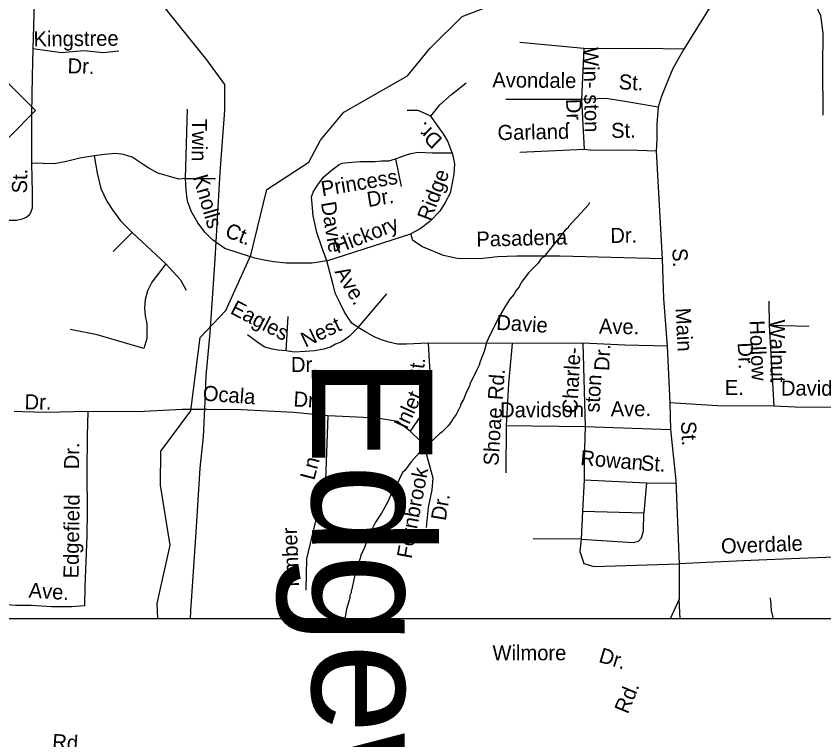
# Model space of a CAD drawing. Extents: x 1553981 to 1780076, y 812965 to 996873.
# Drawn here: x 1632965 to 1633602, y 844957 to 845527 of the extents above; entities that cross this region are included whole.
import ezdxf

# ---------------------------------------------------------------- set-up
doc = ezdxf.new("R2010")
doc.units = 0
for name, color, linetype in [('Default', 7, 'Continuous'), ('Exist Hydrographic Creek Single Shore', 7, 'Continuous'), ('Exist Hydrographic Misc Water Feature', 7, 'Continuous'), ('Exist Road Non-System Type 51 Label', 7, 'Continuous'), ('Exist Utilities Electrical Transmission Line', 7, 'Continuous'), ('Map Preparation Border County Name Lower Right Label', 7, 'Continuous'), ('Map Preparation Border Division and District Label', 7, 'Continuous')]:
    doc.layers.add(name, color=color, linetype=linetype)

msp = doc.modelspace()

# ---------------------------------------------------------------- linework, layer by layer
at = {"layer": 'Default'}
msp.add_lwpolyline([(1632323.05, 848155.4), (1636375.85, 848155.4), (1636375.85, 845052.3), (1632323.05, 845052.3)], close=True, dxfattribs=at)
at = {"layer": 'Exist Hydrographic Creek Single Shore'}
for points in [[(1633273.69, 845479.99), (1633291.58, 845501.65), (1633316.82, 845526.57), (1633348.33, 845538.66), (1633384.82, 845546.53), (1633399.58, 845555.67), (1633434.46, 845603.38), (1633448.33, 845633.05), (1633450.71, 845655.16), (1633439.83, 845696.82), (1633436.7, 845700.17), (1633439.07, 845729.25), (1633449.95, 845766.78)], [(1633077, 845052.3), (1633076.43, 845064.43), (1633086.7, 845110.25), (1633078.95, 845157.59), (1633079.31, 845184.22), (1633103.01, 845216.14), (1633110.34, 845273.94), (1633130.6, 845295.08), (1633150.08, 845338.75), (1633162.66, 845390.39), (1633195.83, 845411.91), (1633205.04, 845429.12), (1633223.46, 845451.25), (1633273.69, 845479.99)]]:
    msp.add_lwpolyline(points, dxfattribs=at)
at = {"layer": 'Exist Hydrographic Misc Water Feature'}
for points in [[(1633417.06, 845380.14), (1633416.04, 845378.15), (1633413.52, 845375.17), (1633400.69, 845361.29), (1633400.18, 845360.3), (1633397.92, 845358.32), (1633383.31, 845339.94), (1633380.79, 845337.21), (1633379.03, 845335.98), (1633376.76, 845332.25), (1633369.22, 845325.07), (1633364.18, 845318.11), (1633361.9, 845314.63), (1633361.64, 845313.64), (1633359.13, 845310.66), (1633357.36, 845307.67), (1633354.08, 845303.71), (1633351.81, 845299.73), (1633350.8, 845298.73), (1633345.24, 845288.79), (1633337.14, 845272.87), (1633335.87, 845269.87), (1633334.06, 845262.9), (1633331.01, 845254.92), (1633330.24, 845251.93), (1633327.97, 845247.96), (1633322.9, 845237.01), (1633322.89, 845236.01), (1633320.11, 845231.03), (1633317.82, 845225.06), (1633315.54, 845221.08), (1633315.53, 845220.08), (1633311.99, 845213.11), (1633309.72, 845210.13), (1633308.71, 845208.14), (1633305.93, 845204.42), (1633300.41, 845198.96), (1633299.15, 845198.23), (1633283.05, 845183.37), (1633276.52, 845175.92), (1633271.47, 845168.97), (1633269.8, 845167.37)], [(1633269.8, 845167.37), (1633264.42, 845156.41), (1633262.9, 845154.4), (1633259.82, 845148.35), (1633258.78, 845145.32), (1633253.14, 845135.34), (1633248.55, 845128.41), (1633244.97, 845121.46), (1633244.44, 845119.47), (1633241.87, 845114.51), (1633239.79, 845108.54), (1633236.7, 845101.58), (1633236.69, 845100.58), (1633234.09, 845093.62), (1633231.71, 845084.65), (1633229.84, 845075.68), (1633229.33, 845074.69), (1633229.31, 845072.69), (1633228.28, 845070.7), (1633228.25, 845068.7), (1633225.63, 845059.75), (1633224.29, 845052.3)], [(1633559.18, 845068.88), (1633559.71, 845066.72), (1633560.4, 845058.73), (1633561.96, 845052.3)]]:
    msp.add_lwpolyline(points, dxfattribs=at)
at = {"layer": 'Exist Utilities Electrical Transmission Line'}
msp.add_lwpolyline([(1633102.52, 845052.3), (1633102.88, 845058.57), (1633107.42, 845124.47), (1633110.13, 845170.89), (1633112.76, 845195.6), (1633114.2, 845223.31), (1633115.03, 845243.53), (1633118.05, 845277.46), (1633121.98, 845335.64), (1633126.04, 845403.79), (1633129.56, 845452.95), (1633129.62, 845473.18), (1633115.46, 845492.41), (1633086.06, 845529.07), (1633072.35, 845547.29)], dxfattribs=at)
at = {"layer": 'Map Preparation Border County Name Lower Right Label'}
for p, q in [((1633558.46, 845302.55), (1633558.67, 845283.49)), ((1633558.67, 845283.49), (1633590.18, 845282.88)), ((1633558.67, 845283.49), (1633562.36, 845219.82)), ((1633412, 845269.28), (1633413.69, 845203.65)), ((1633480.4, 845222.27), (1633480.92, 845201.3)), ((1633351.46, 845204.53), (1633351.05, 845167.17)), ((1633351.46, 845204.53), (1633413.69, 845203.65)), ((1633413.69, 845203.65), (1633480.92, 845201.3)), ((1633480.92, 845201.3), (1633485.17, 845161.27)), ((1633485.17, 845161.27), (1633487.86, 845095.51))]:
    msp.add_line(p, q, dxfattribs=at)
for points in [[(1632982.66, 845666.1), (1632982.31, 845642.82), (1632981.83, 845612.47), (1632980.14, 845573.5), (1632979.66, 845545.56), (1632978.94, 845519.42), (1632978.22, 845501.12)], [(1633544.45, 845588.45), (1633565.76, 845570.67), (1633581.35, 845555.65), (1633593.76, 845539.18), (1633599.25, 845527.34), (1633600.98, 845513.47), (1633600.69, 845486.89), (1633600.98, 845449.04)], [(1633531.17, 845566.78), (1633511.61, 845533.41), (1633491.4, 845501.05)], [(1633412.62, 845501.42), (1633362.1, 845506.04)], [(1632978.22, 845501.12), (1632977.73, 845479.49), (1632977.25, 845450.34), (1632977.25, 845411.08), (1632977.73, 845387.76), (1632977.73, 845375.72), (1632976.77, 845372.83), (1632975.61, 845370.5), (1632973.59, 845368.54), (1632970.06, 845367.08), (1632965.56, 845365.9), (1632959.81, 845365.99), (1632953.8, 845365.56), (1632947.09, 845363.13)], [(1633046.01, 845499.37), (1633034, 845498.04), (1633018.52, 845499.53), (1633001.03, 845498.03), (1632978.22, 845501.12)], [(1633412.62, 845501.42), (1633410.89, 845461.26)], [(1633491.4, 845501.05), (1633458.82, 845501.42), (1633426.19, 845501.13), (1633412.62, 845501.42)], [(1633491.4, 845501.05), (1633482.78, 845485.82), (1633477.87, 845473.68), (1633473.54, 845462.99), (1633471.23, 845455.19)], [(1633291.94, 845448.22), (1633299.22, 845457.19), (1633308.42, 845465.24), (1633319.91, 845474.44)], [(1633410.89, 845461.26), (1633351.13, 845461.26)], [(1633471.23, 845455.19), (1633448.14, 845459.24), (1633430.24, 845462.13), (1633410.89, 845461.26)], [(1633410.89, 845461.26), (1633412.91, 845421.97)], [(1633098.63, 845399.1), (1633100.36, 845453.74)], [(1633471.23, 845455.19), (1633470.08, 845442.19), (1633470.08, 845430.06), (1633469.79, 845420.52)], [(1633291.94, 845448.22), (1633281.98, 845452.59), (1633273.36, 845452.59)], [(1633308.99, 845419.23), (1633305.54, 845428.43), (1633302.09, 845434.18), (1633299.22, 845438.21), (1633291.94, 845448.22)], [(1633412.91, 845421.97), (1633362.1, 845419.66)], [(1633469.79, 845420.52), (1633455.06, 845421.1), (1633439.19, 845421.39), (1633420.13, 845421.1), (1633412.91, 845421.97)], [(1633026.79, 845416.93), (1633015.29, 845415.2), (1633004.95, 845412.33), (1632995.18, 845410.6), (1632977.25, 845411.08)], [(1633098.63, 845399.1), (1633093.46, 845398.53), (1633085.41, 845400.83), (1633076.79, 845403.13), (1633069.89, 845407.15), (1633065.3, 845410.03), (1633056.68, 845415.78), (1633049.78, 845418.08), (1633043.46, 845418.65), (1633034.83, 845418.08), (1633026.79, 845416.93)], [(1633026.79, 845416.93), (1633029.09, 845403.13), (1633031.96, 845391.05), (1633036.56, 845381.27), (1633041.16, 845374.37), (1633047.48, 845365.75), (1633056.68, 845356.54)], [(1633264.16, 845414.63), (1633272.21, 845417.5), (1633276.23, 845418.65), (1633281.98, 845419.81), (1633293.47, 845419.23), (1633308.99, 845419.23)], [(1633308.99, 845419.23), (1633310.72, 845410.6), (1633310.14, 845402.55), (1633308.99, 845395.65), (1633307.27, 845387.6), (1633303.24, 845380.12), (1633299.22, 845373.22), (1633291.17, 845365.17), (1633283.7, 845359.42), (1633276.23, 845355.39)], [(1633469.79, 845420.52), (1633474.41, 845335.8)], [(1633198.64, 845378.97), (1633198.06, 845384.72), (1633199.21, 845388.17), (1633202.66, 845393.93), (1633207.83, 845400.25), (1633213.58, 845405.43), (1633219.9, 845410.03), (1633222.2, 845411.18), (1633226.8, 845411.75), (1633236.57, 845412.33), (1633248.07, 845412.33), (1633253.24, 845412.9), (1633258.99, 845412.9), (1633264.16, 845414.63)], [(1633264.16, 845414.63), (1633268.76, 845392.78)], [(1633210.13, 845334.12), (1633198.64, 845332.39), (1633187.72, 845332.39), (1633177.95, 845332.39), (1633168.18, 845333.54), (1633160.71, 845334.69), (1633153.23, 845336.42), (1633141.74, 845339.87), (1633129.67, 845343.89), (1633119.9, 845350.79), (1633114.15, 845356.54), (1633108.4, 845364.02), (1633103.23, 845373.22), (1633100.36, 845381.27), (1633099.21, 845389.9), (1633098.63, 845399.1)], [(1633098.63, 845399.1), (1633122.2, 845399.1)], [(1633210.13, 845334.12), (1633206.11, 845345.04), (1633202.09, 845356.54), (1633199.21, 845369.77), (1633198.64, 845378.97)], [(1633056.68, 845356.54), (1633041.73, 845341.59)], [(1633056.68, 845356.54), (1633083.11, 845331.81)], [(1633210.13, 845334.12), (1633276.23, 845355.39)], [(1633474.41, 845335.8), (1633393.95, 845337.83), (1633359.88, 845337.83), (1633344.58, 845337.25), (1633331.01, 845335.8), (1633312.82, 845336.09), (1633302.14, 845338.41), (1633285.39, 845345.34), (1633277.88, 845350.25), (1633276.23, 845355.39)], [(1633234.85, 845281.78), (1633229.68, 845285.23), (1633226.8, 845289.26), (1633223.93, 845293.86), (1633220.48, 845300.76), (1633217.03, 845308.24), (1633214.73, 845316.29), (1633210.13, 845334.12)], [(1633474.41, 845335.8), (1633475.41, 845304.53), (1633477.17, 845280.74), (1633478.34, 845266.93)], [(1633083.11, 845331.81), (1633077.37, 845324.34), (1633072.19, 845317.44), (1633068.74, 845310.54), (1633067.02, 845303.64), (1633066.45, 845297.31), (1633067.02, 845290.98), (1633068.17, 845284.66), (1633068.17, 845278.33), (1633068.17, 845273.15), (1633065.87, 845265.1), (1633029.09, 845276.03), (1633007.82, 845280.06)], [(1633083.11, 845331.81), (1633094.61, 845319.16), (1633099.21, 845311.11)], [(1633234.85, 845281.78), (1633257.26, 845308.24)], [(1633177.95, 845263.38), (1633179.67, 845290.41)], [(1633234.85, 845281.78), (1633227.95, 845274.88), (1633223.93, 845272), (1633221.05, 845270.28), (1633217.03, 845268.55), (1633213.01, 845266.25), (1633207.83, 845264.53), (1633200.36, 845263.38), (1633192.89, 845262.8), (1633184.27, 845262.23), (1633177.95, 845263.38)], [(1633289.87, 845269.28), (1633272.78, 845268.55), (1633265.88, 845268.55), (1633258.99, 845270.28), (1633253.24, 845272), (1633247.49, 845274.3), (1633240.6, 845278.33), (1633234.85, 845281.78)], [(1633177.95, 845263.38), (1633171.63, 845263.95), (1633167.03, 845264.53), (1633161.28, 845266.25), (1633156.68, 845269.13), (1633147.49, 845276.03)], [(1633289.87, 845269.28), (1633290.75, 845254.88), (1633291.34, 845246.95), (1633290.75, 845239.02), (1633290.94, 845231.46), (1633289.63, 845224.98), (1633288.02, 845219.71), (1633286.03, 845215.38), (1633280.97, 845207.55), (1633275.68, 845199.94)], [(1633356.22, 845268.99), (1633289.87, 845269.28)], [(1633356.22, 845268.99), (1633353.28, 845237.55), (1633351.46, 845204.53)], [(1633412, 845269.28), (1633356.22, 845268.99)], [(1633478.34, 845266.93), (1633444.88, 845267.81), (1633412, 845269.28)], [(1633478.34, 845266.93), (1633480.4, 845222.27)], [(1633562.36, 845219.82), (1633518.13, 845220.03), (1633480.4, 845222.27)], [(1633697.67, 845216.16), (1633637.37, 845218.63), (1633579.14, 845218.86), (1633562.36, 845219.82)], [(1633021.57, 845215.5), (1632988.71, 845214.86), (1632970.21, 845215.18), (1632963.51, 845215.5)], [(1633021.57, 845215.5), (1633021.15, 845196.43), (1633020.97, 845167.44), (1633021.25, 845137.22), (1633020.96, 845117.74), (1633020.15, 845097.49), (1633019.34, 845077.52), (1633019.11, 845062.55)], [(1633210.9, 845212.01), (1633184.1, 845214.88), (1633142.63, 845216.8), (1633115.83, 845217.11), (1633096.05, 845217.11), (1633061.13, 845215.18), (1633021.57, 845215.5)], [(1633210.9, 845212.01), (1633209, 845161.74), (1633200.55, 845127.03), (1633194.14, 845099.62), (1633193.55, 845074.83)], [(1633275.68, 845199.94), (1633265.77, 845207.54), (1633249.82, 845210.41), (1633222.39, 845211.69), (1633210.9, 845212.01)], [(1633275.68, 845199.94), (1633283.7, 845192.54), (1633288.72, 845181.36), (1633293.74, 845163.32), (1633292.83, 845153.73), (1633290.09, 845139.8), (1633288.27, 845124.27)], [(1633413.69, 845203.65), (1633412.86, 845177.12), (1633412.82, 845161.71)], [(1633412.82, 845161.71), (1633411.48, 845137.1)], [(1633412.82, 845161.71), (1633462, 845159.3)], [(1633462, 845159.3), (1633459.86, 845135.76)], [(1633462, 845159.3), (1633484.72, 845159.03)], [(1633411.48, 845137.1), (1633410.68, 845114.9)], [(1633410.68, 845114.9), (1633451.58, 845112.49), (1633455.85, 845113.29), (1633457.99, 845115.97), (1633459.6, 845121.58), (1633459.86, 845135.76)], [(1633411.48, 845137.1), (1633459.86, 845135.76)], [(1633410.68, 845114.9), (1633372.72, 845115.16)], [(1633410.68, 845114.9), (1633409.61, 845105.27), (1633412.55, 845095.9), (1633420.57, 845093.5), (1633487.86, 845095.51)], [(1633695.45, 845087.99), (1633678.2, 845087.14), (1633674.94, 845087.16), (1633672.19, 845087.19), (1633668.21, 845087.97), (1633647, 845093.15), (1633624.32, 845098.59), (1633616.83, 845100.42), (1633613.84, 845100.93), (1633610.59, 845100.72), (1633582.35, 845099.69), (1633544.35, 845098.29), (1633509.35, 845096.57), (1633487.86, 845095.51)], [(1633487.86, 845095.51), (1633487.77, 845067.82)], [(1633487.77, 845067.82), (1633480.73, 845052.3)], [(1633488.69, 845052.3), (1633487.77, 845067.82)], [(1633019.11, 845062.55), (1633008.87, 845061.7), (1632993.13, 845061.67), (1632976.92, 845062.68), (1632964.94, 845062.84), (1632953.2, 845063.53)]]:
    msp.add_lwpolyline(points, dxfattribs=at)
at = {"layer": 'Map Preparation Border Division and District Label'}
msp.add_lwpolyline([(1632897.27, 845452.58), (1632938.9, 845494.2), (1632980.52, 845452.58), (1632938.9, 845410.95)], close=True, dxfattribs=at)

# ---------------------------------------------------------------- texts
at = {"layer": 'Exist Road Non-System Type 51 Label'}
for s, height, rotation, p in [('Kingstree', 11.875, 0.46335, (1632978.93, 845503.08)), ('Win- ston', 11.875, 270.95334, (1633412.32, 845502.39)), ('Dr.', 11.875, 358.51042, (1633005.6, 845481.91)), ('Avondale', 11.875, 359.48586, (1633340.49, 845470.87)), ('St.', 11.875, 356.57724, (1633439.88, 845469.44)), ('Dr.', 11.875, 272.06446, (1633398.61, 845461.64)), ('Twin', 11.875, 269.6209, (1633103.84, 845446.12)), ('Dr.', 11.875, 136.29223, (1633302.01, 845430.04)), ('Garland', 11.875, 1.1332, (1633344.71, 845429.25)), ('St.', 11.875, 0.79971, (1633434.24, 845430.92)), ('St.', 11.875, 89.09781, (1632973.7, 845387.2)), ('Princess', 11.875, 9.43706, (1633206.55, 845384.97)), ('Ridge', 11.875, 69.02209, (1633291.98, 845364.82)), ('Knolls', 11.875, 286.3616, (1633104.44, 845400.2)), ('Dr.', 11.875, 9.43706, (1633242.7, 845376.52)), ('Davie', 11.875, 279.30027, (1633205.36, 845379.97)), ('Hickory', 11.875, 21.20583, (1633218.31, 845339.73)), ('Ct.', 11.875, 338.70309, (1633128.99, 845353.48)), ('Pasadena', 11.875, 1.41655, (1633328.08, 845345.32)), ('Dr.', 11.875, 0.60039, (1633433.59, 845348.26)), ('S.', 11.875, 273.04795, (1633482.36, 845343.92)), ('Ave.', 11.875, 300.70534, (1633215.92, 845325.56)), ('Eagles', 11.875, 332.60751, (1633133.17, 845293.17)), ('Main', 11.875, 273.04795, (1633484.87, 845296.88)), ('Nest', 11.875, 25.50988, (1633193.16, 845265.79)), ('Davie', 11.875, 356.64153, (1633343.4, 845279.89)), ('Ave.', 11.875, 359.0427, (1633424.47, 845276.87)), ('Walnut', 11.875, 270.62162, (1633559.27, 845287.87)), ('Hollow', 11.875, 272.40442, (1633543.18, 845287.13)), ('Dr.', 11.875, 272.40442, (1633533.89, 845269.74)), ('Charle-', 11.875, 87.02396, (1633407.48, 845213.73)), ('Dr.', 11.875, 87.02396, (1633432.55, 845247.25)), ('Dr.', 11.875, 0.46551, (1633181.85, 845246.52)), ('St.', 11.875, 83.12409, (1633285.48, 845238.22)), ('Edgewood', 95, 270.03788, (1633198.25, 845258.56)), ('Rd.', 11.875, 85.88345, (1633348.75, 845224.25)), ('ston', 11.875, 87.02396, (1633424.94, 845214.44)), ('E.', 11.875, 359.73036, (1633523.66, 845228.57)), ('Davidson', 11.875, 359.77159, (1633568.01, 845228.08)), ('Ocala', 11.875, 355.66162, (1633111.97, 845224.23)), ('Dr.', 11.875, 356.09404, (1633183.51, 845219.61)), ('Inlet', 11.875, 65.36244, (1633273.15, 845200.78)), ('Dr.', 11.875, 359.16744, (1632971.75, 845217.29)), ('Shoae', 11.875, 86.22683, (1633345.24, 845172.57)), ('Davidson', 11.875, 0.20513, (1633346.67, 845210.86)), ('Ave.', 11.875, 0.15012, (1633433.85, 845211.79)), ('St.', 11.875, 272.62322, (1633489.2, 845207.7)), ('Dr.', 11.875, 89.62874, (1633014.83, 845170)), ('Ln.', 11.875, 75.53836, (1633200.18, 845160.88)), ('Rowan', 11.875, 355.18682, (1633409.56, 845173.37)), ('St.', 11.875, 356.16536, (1633457.28, 845169.31)), ('Fernbrook', 11.875, 79.4081, (1633276.77, 845099.12)), ('Edgefield', 11.875, 89.13158, (1633014.3, 845084.03)), ('Dr.', 11.875, 80.4747, (1633303.7, 845129.03)), ('Timber', 11.875, 92.27562, (1633188.43, 845074.9)), ('Overdale', 11.875, 2.11634, (1633520.99, 845103.58)), ('Ave.', 11.875, 356.45534, (1632974.8, 845068.97)), ('Wilmore', 11.875, 0.02106, (1633340.65, 845019.58)), ('Dr.', 11.875, 343.13985, (1633423.72, 845018.45)), ('Rd.', 11.875, 67.58271, (1633447.29, 844976.71)), ('Rd.', 11.875, 356.12086, (1632993.35, 844949.84))]:
    msp.add_text(s, height=height, rotation=rotation, dxfattribs=at).set_placement(p)

doc.saveas('drawing.dxf')
